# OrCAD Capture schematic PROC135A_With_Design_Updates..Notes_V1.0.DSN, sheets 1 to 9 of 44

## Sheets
1 01. TABLE OF CONTENTS: title: TABLE OF CONTENTS; rev: A
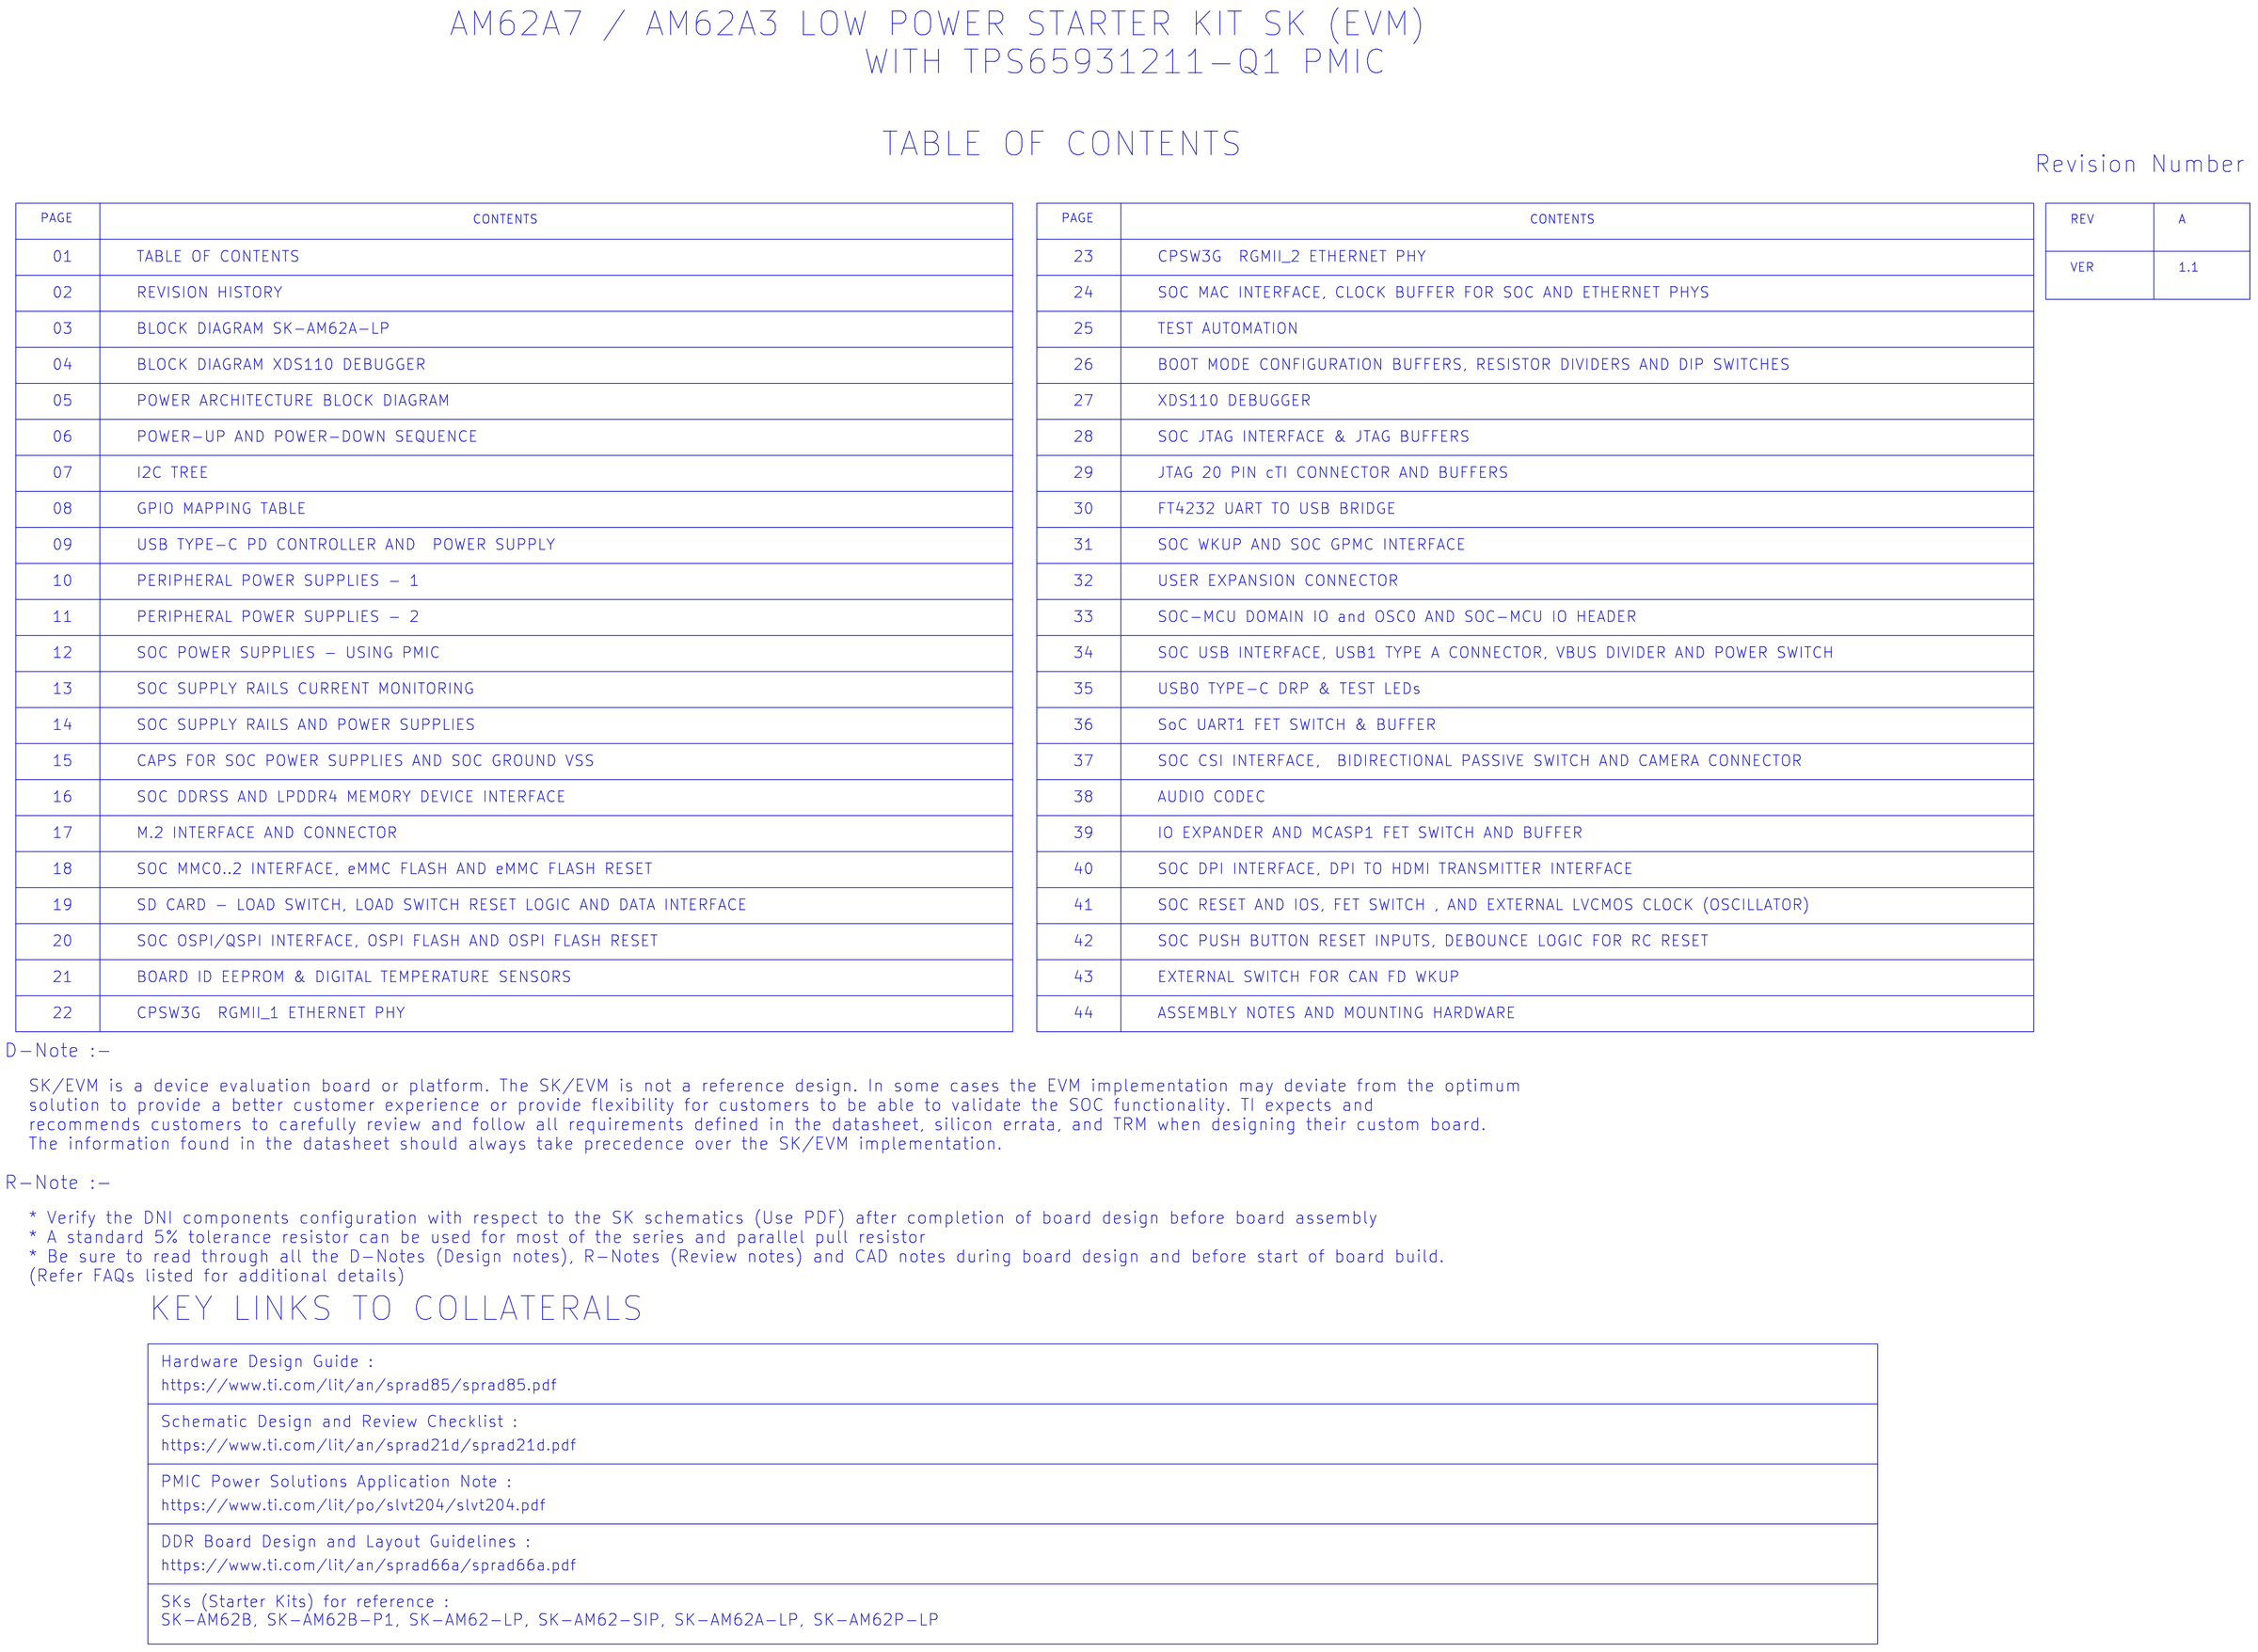
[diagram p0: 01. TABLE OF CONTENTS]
2 02. REVISION HISTORY: title: REVISION HISTORY
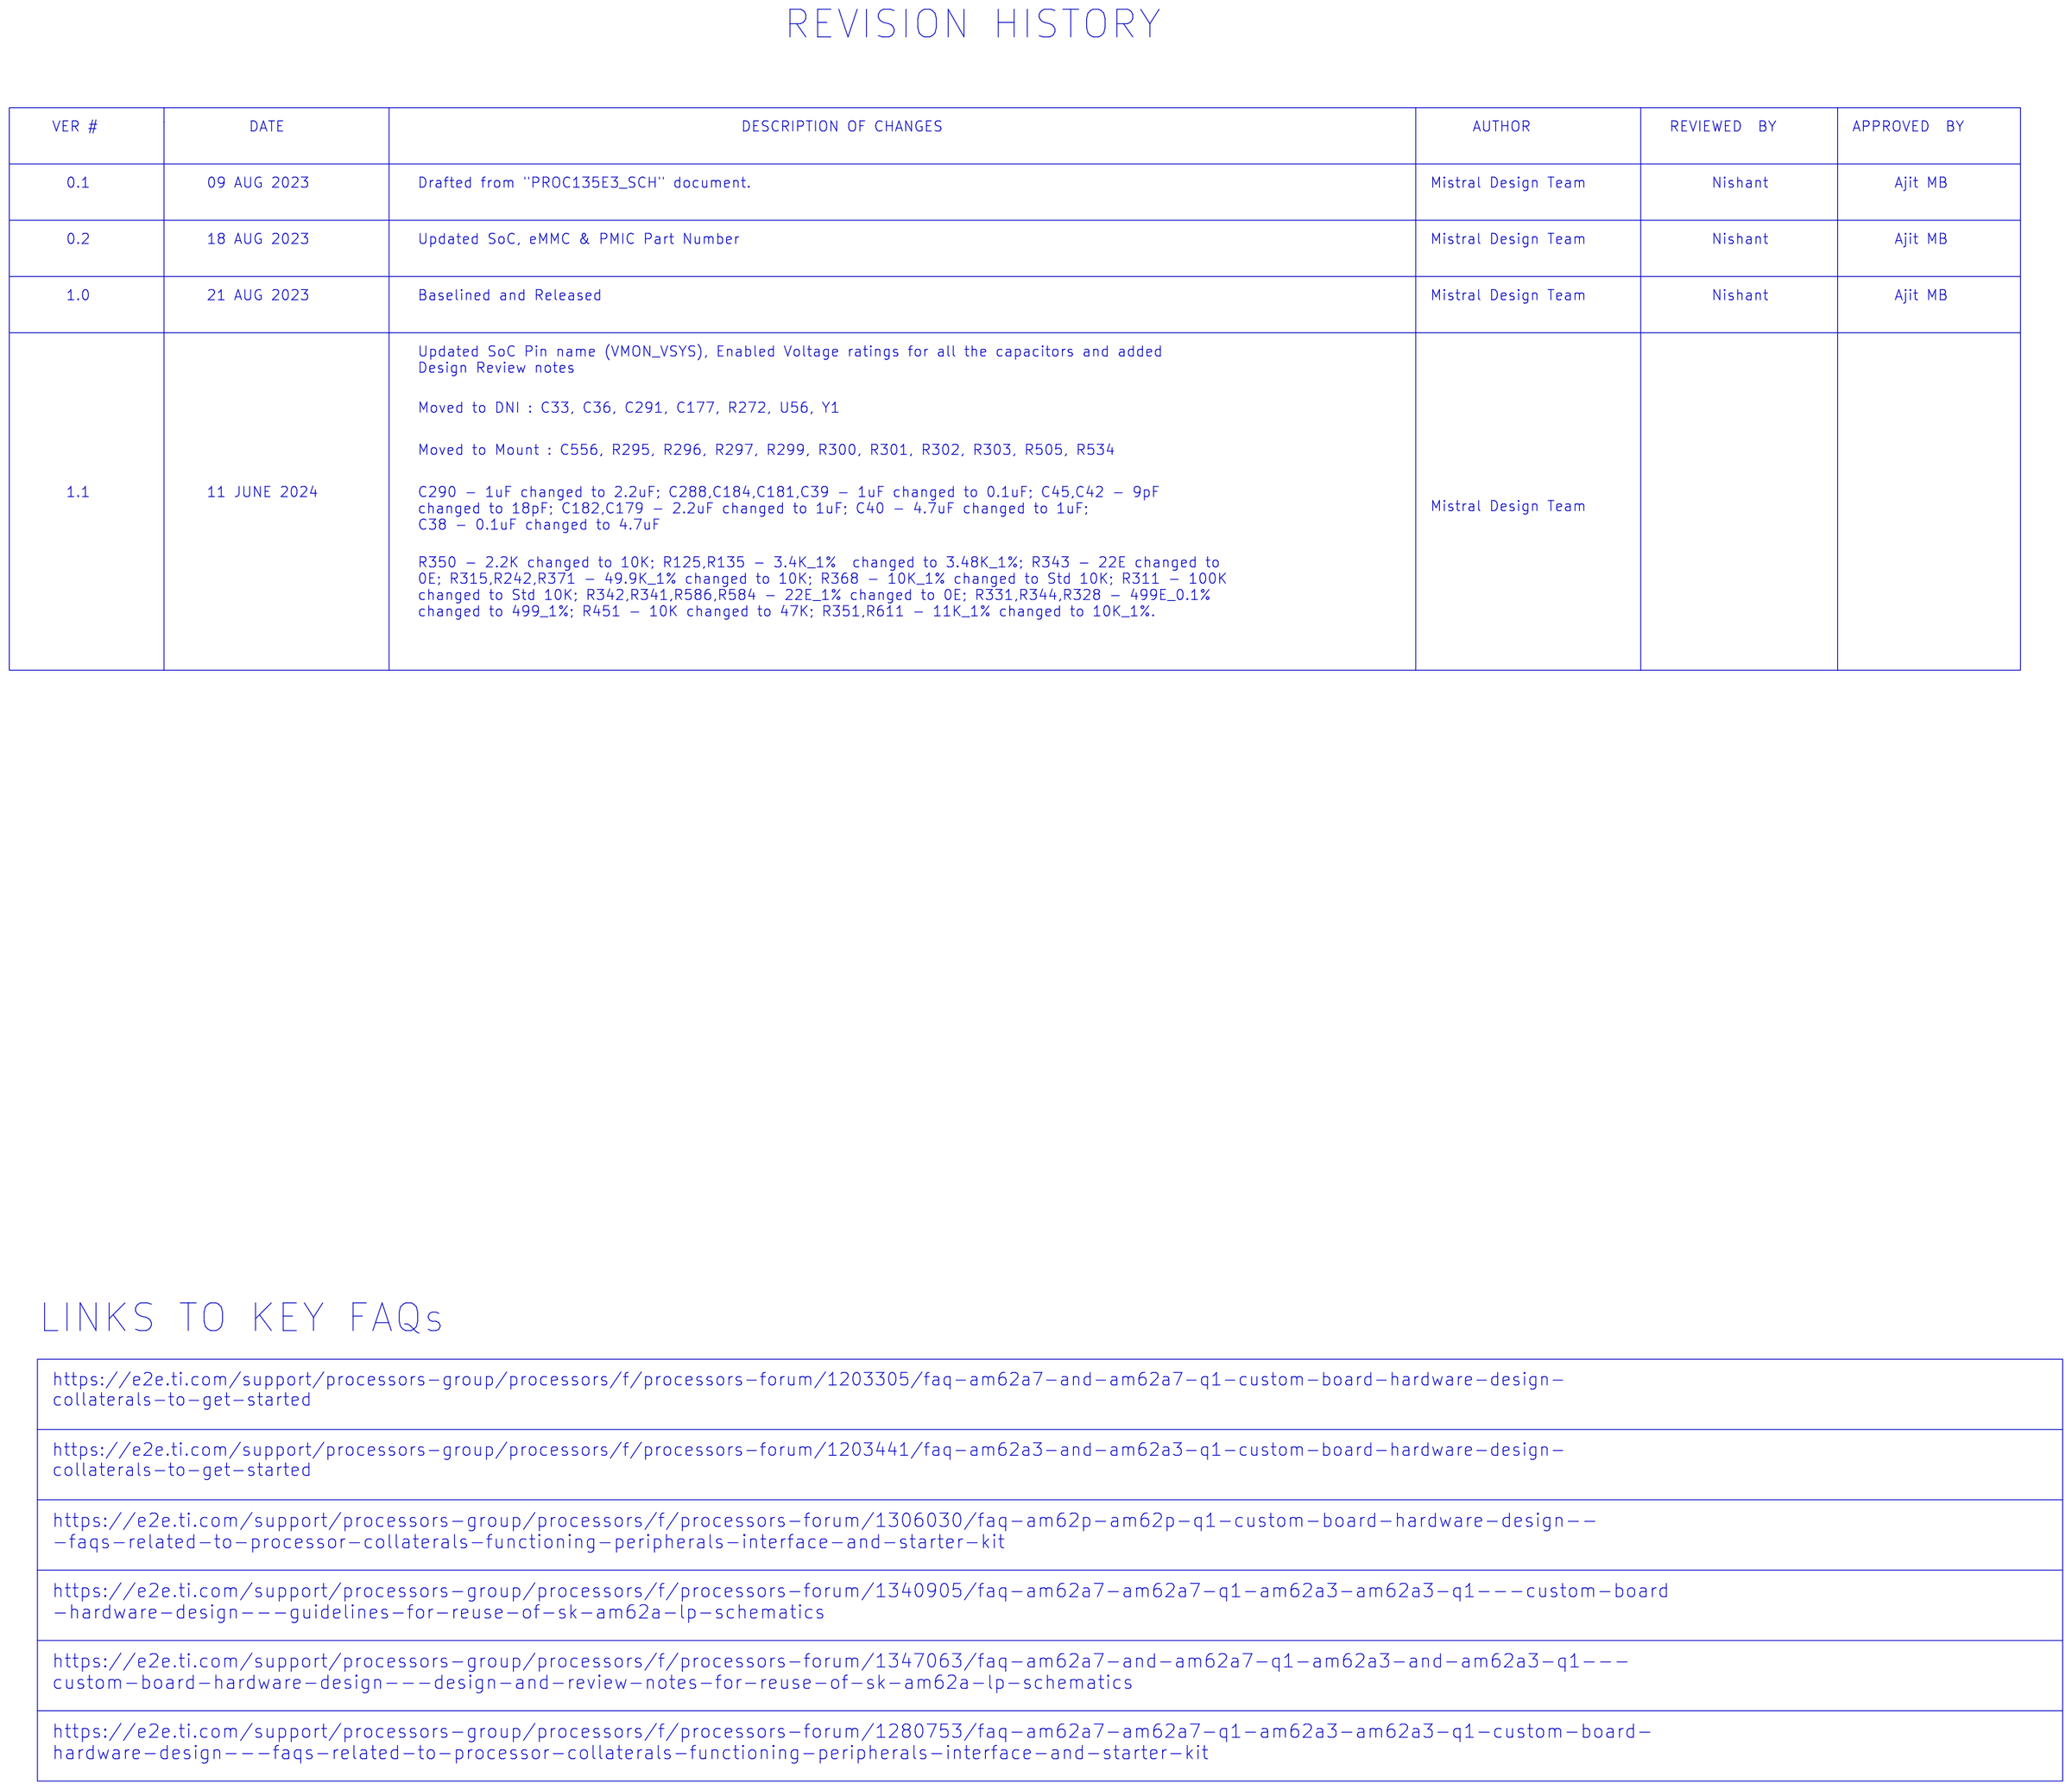
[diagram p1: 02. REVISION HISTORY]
3 03. BLOCK DGM AM62A-SKEVM: title: BLOCK DIAGRAM AM62A_ SKEVM
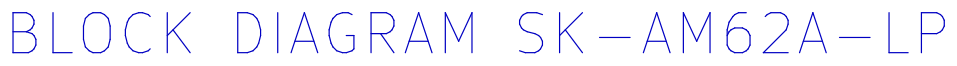
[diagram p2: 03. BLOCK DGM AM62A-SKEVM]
4 04. BLOCK DIAGRAM_XDS110: title: BLOCK DIAGRAM_XDS110
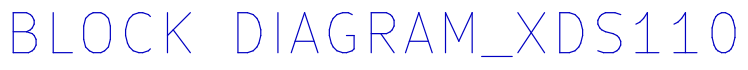
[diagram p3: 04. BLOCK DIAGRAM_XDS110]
5 05. POWER BLOCK DGM: title: POWER BLOCK DGM
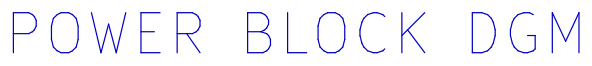
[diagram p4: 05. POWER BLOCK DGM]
6 06. POWER SEQUENCE: title: POWER SEQUENCE
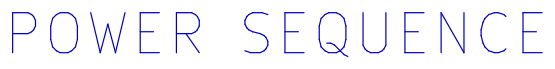
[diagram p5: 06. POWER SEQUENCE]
7 07. I2C TREE: title: I2C TREE
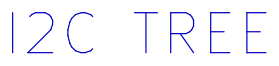
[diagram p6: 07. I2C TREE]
8 08. GPIO MAPPING TABLE: title: GPIO MAPPING TABLE
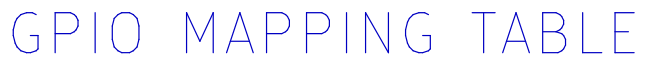
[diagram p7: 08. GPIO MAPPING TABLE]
9 09. USB TYPE-C POWER: size C; title: USB TYPE-C
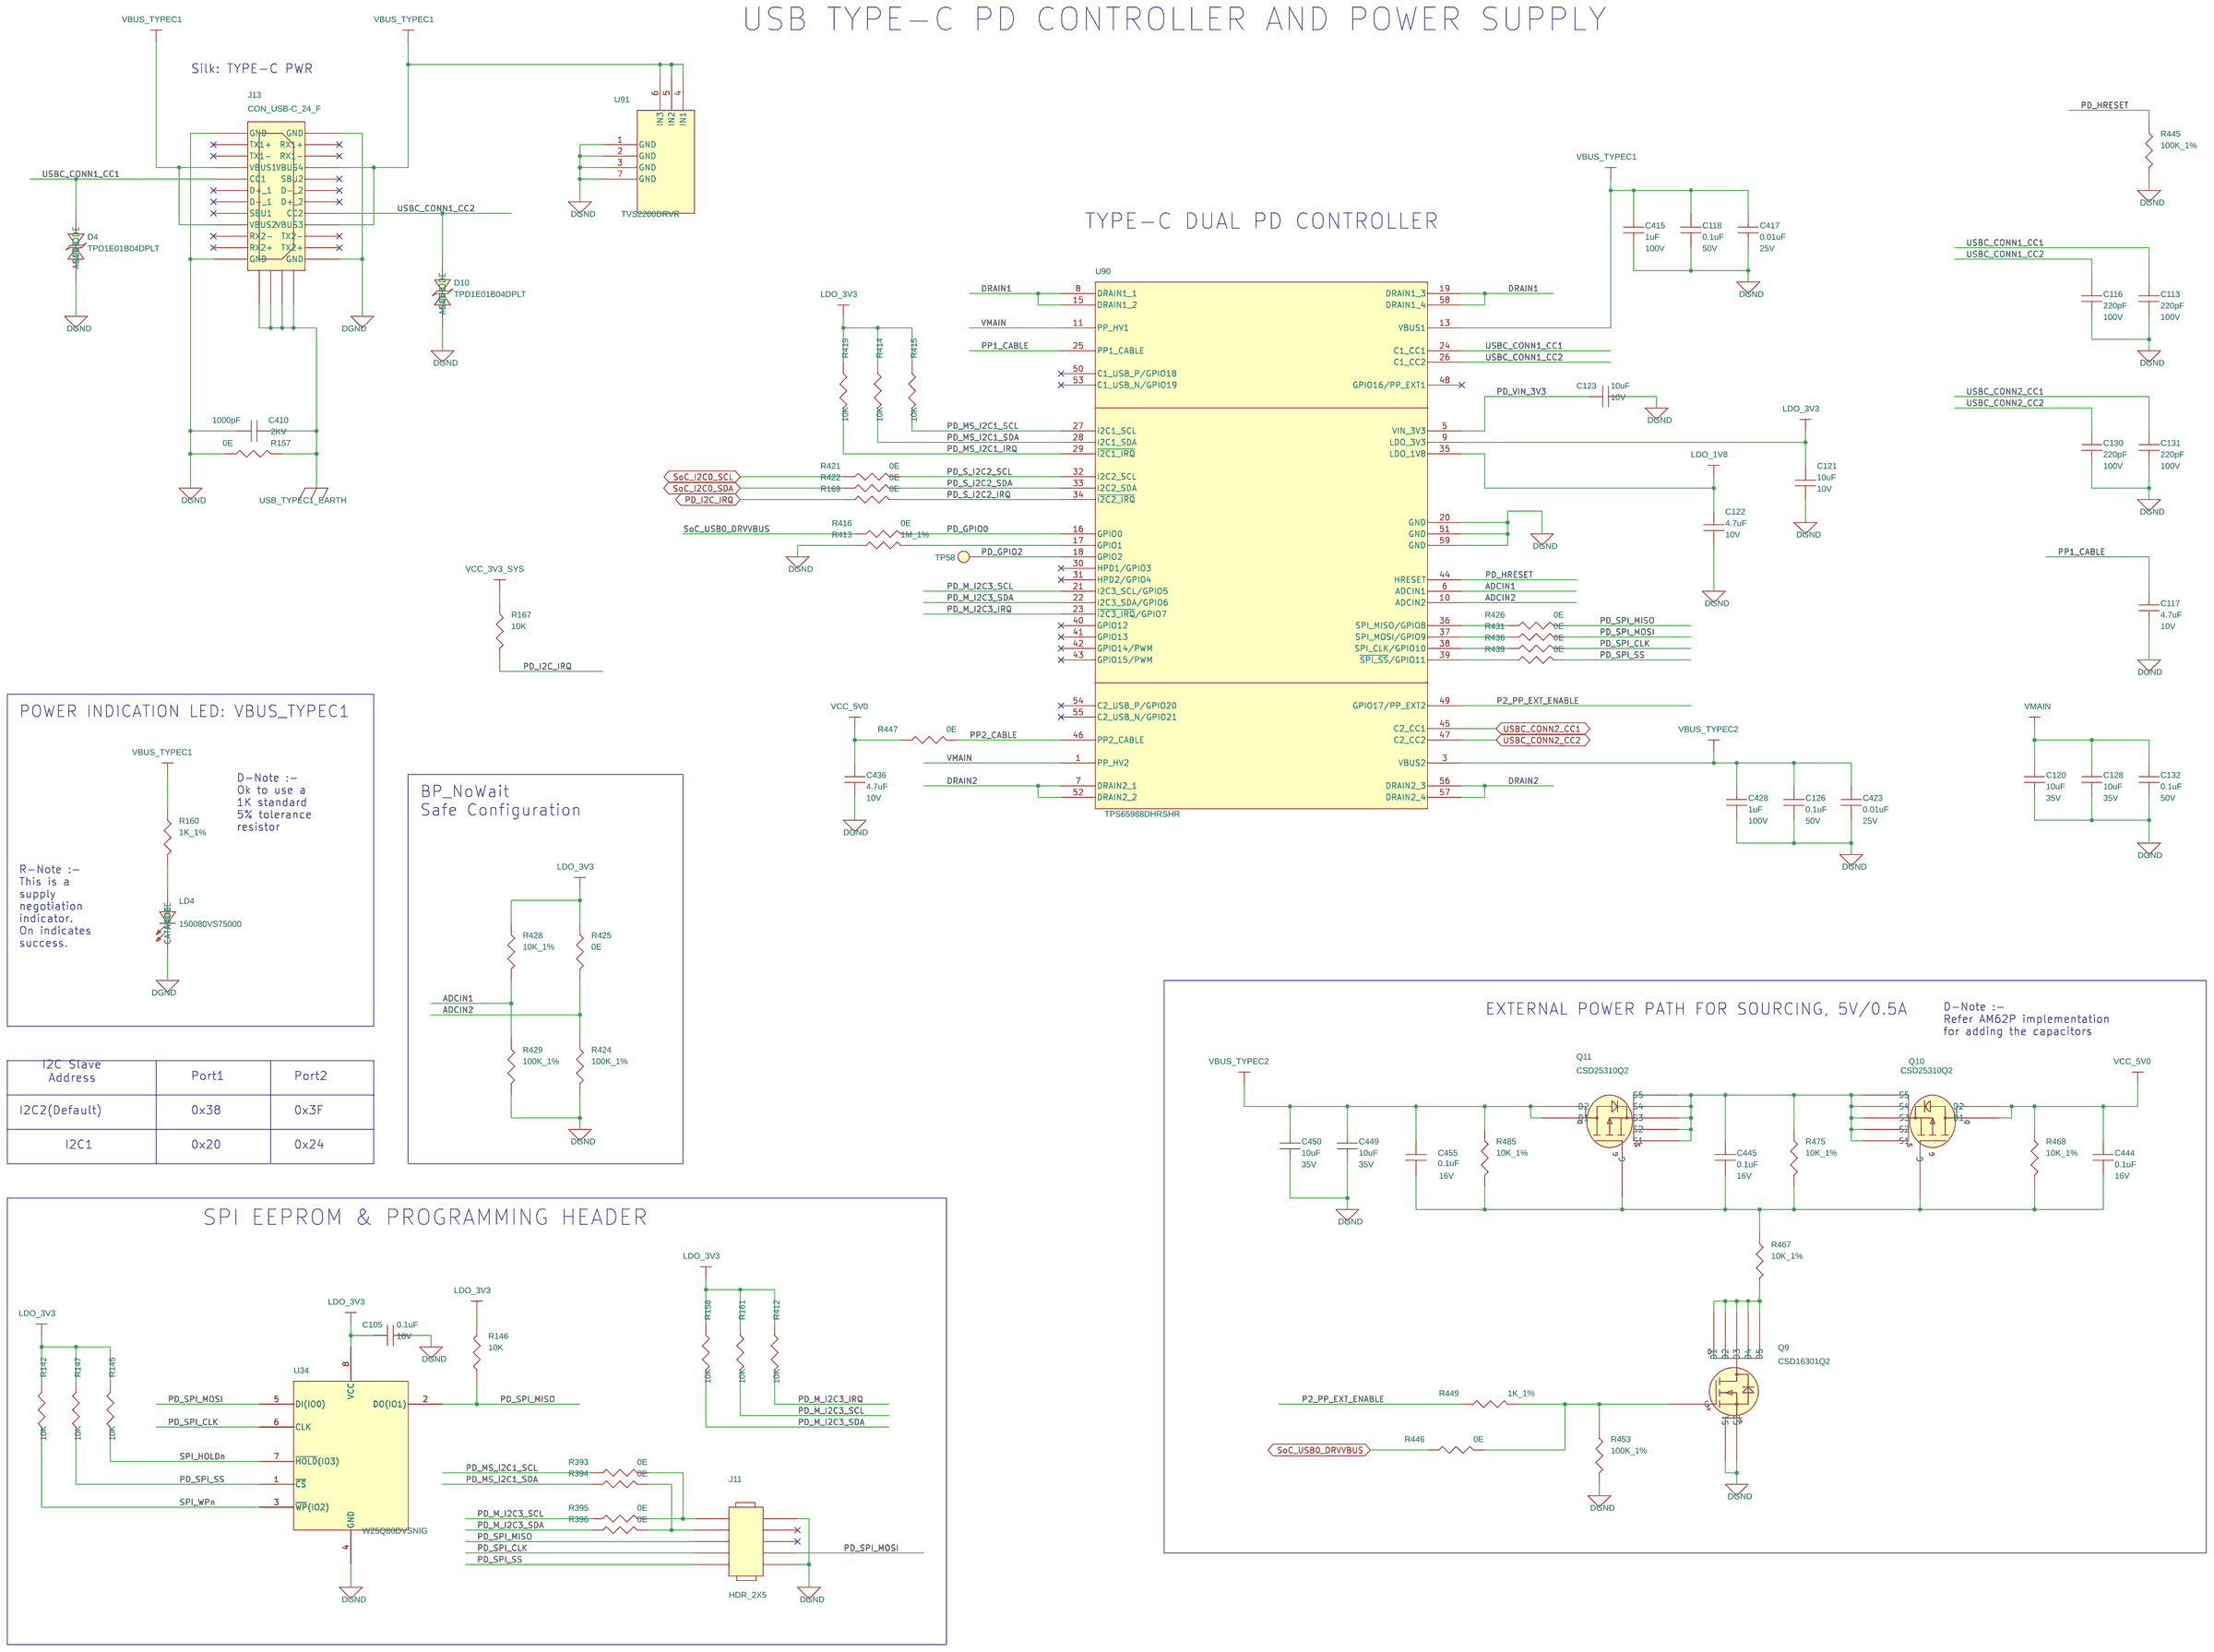
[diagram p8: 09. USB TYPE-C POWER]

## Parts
C105  0.1uF  [CAP0201_0-5]
C113  220pF  [CAP0402_0-75]
C116  220pF  [CAP0402_0-75]
C117  4.7uF  [CAP0402_0-75]
C118  0.1uF  [CAP0402_0-75]
C120  10uF  [CAP0603_1]
C121  10uF  [CAP0402_0-75]
C122  4.7uF  [CAP0402_0-75]
C123  10uF  [CAP0402_0-75]
C126  0.1uF  [CAP0402_0-75]
C128  10uF  [CAP0603_1]
C130  220pF  [CAP0402_0-75]
C131  220pF  [CAP0402_0-75]
C132  0.1uF  [CAP0402_0-75]
C410  1000pF  [CAP1206_1-75]
C415  1uF  [CAP0805_1-5]
C417  0.01uF  [CAP0201_0-5]
C423  0.01uF  [CAP0201_0-5]
C428  1uF  [CAP0805_1-5]
C436  4.7uF  [CAP0402_0-75]
C444  0.1uF  [CAP0201_0-5]
C445  0.1uF  [CAP0201_0-5]
C449  10uF  [CAP0603_1]
C450  10uF  [CAP0603_1]
C455  0.1uF  [CAP0201_0-5]
D4  TPD1E01B04DPLT  [DIO_DFN0201_0-4]
D10  TPD1E01B04DPLT  [DIO_DFN0201_0-4]
J11  HDR_2X5  [HDR_2X5_PEC05DAAN_S_T_8-6]
J13  CON_USB-C_24_F  [CON_USBC24_2012670_S_R_S_3-9]
LD4  150080VS75000  [LED_150080VS75000_80X50_SMD_0-8]
Q9  CSD16301Q2  [WSON6_CSD13202Q2_80X80_0-8]
Q10  CSD25310Q2  [SON6_CSD17313Q2_80X80]
Q11  CSD25310Q2  [SON6_CSD17313Q2_80X80]
R142  10K  [RES0201_0-5]
R145  10K  [RES0201_0-5]
R146  10K  [RES0201_0-5]
R147  10K  [RES0201_0-5]
R157  0E  [RES0603_0-75]
R158  10K  [RES0201_0-5]
R160  1K_1%  [RES0402_0-5]
R161  10K  [RES0201_0-5]
R167  10K  [RES0201_0-5]
R169  0E  [RES0201_0-5]
R393  0E  [RES0201_0-5]
R394  0E  [RES0201_0-5]
R395  0E  [RES0201_0-5]
R396  0E  [RES0201_0-5]
R412  10K  [RES0201_0-5]
R413  1M_1%  [RES0402_0-5]
R414  10K  [RES0201_0-5]
R415  10K  [RES0201_0-5]
R416  0E  [RES0201_0-5]
R419  10K  [RES0201_0-5]
R421  0E  [RES0201_0-5]
R422  0E  [RES0201_0-5]
R424  100K_1%  [RES0402_0-5]
R425  0E  [RES0201_0-5]
R426  0E  [RES0201_0-5]
R428  10K_1%  [RES0201_0-5]
R429  100K_1%  [RES0402_0-5]
R431  0E  [RES0201_0-5]
R436  0E  [RES0201_0-5]
R439  0E  [RES0201_0-5]
R445  100K_1%  [RES0201_0-5]
R446  0E  [RES0201_0-5]
R447  0E  [RES0402_0-5]
R449  1K_1%  [RES0402_0-5]
R453  100K_1%  [RES0402_0-5]
R467  10K_1%  [RES0201_0-5]
R468  10K_1%  [RES0201_0-5]
R475  10K_1%  [RES0201_0-5]
R485  10K_1%  [RES0201_0-5]
TP58  TP20_SMD  [TP20_SMD]
U34  W25Q80DVSNIG  [SOIC8_1-8]
U90  TPS65988DHRSHR  [VQFN56_TPS65987D_280X280_1]
U91  TVS2200DRVR  [SON6_25-59_85X85_0-8]

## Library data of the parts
C105 C444 C445 C455 = CAP: CAP CERAMIC 0.1uF 16V 10% X5R 0201; Chkd/date: MANIRAJA/230118; Crtd /date: MANIRAJA/230118; Custom_Duty: 15%; Customs_HS_Code: 85322990; Distributor_name: DIGIKEY; Distributor_part_number: 490-14305-1-ND; Footprint Path: Y:\MIS_DATABASE\Library\ALTIUM_TOOL\PCB_FOOTPRINTS\Altium_Footprint_Lib.PcbLib; Height: 0.33MM; Library Path: Y:\MIS_DATABASE\Library\ALTIUM_TOOL\SCHEMATICS_PARTS\MS_DISCRETE_Library.schlib; Mfr_name: MURATA; Mfr_part_number: GRM033R61C104KE14D; Mistral Part No: 120009030072-R; Package: 0201; Part_type: CAPACITORS\CERAMIC; Project: TI_MAXIE_CPB; RoHS: RoHS; Temperature: -55°C+85°C; Tolerance: 10%; Voltage: 16V; Wattage: NA; Weight: 0.33mg; Datasheet: Y:\MIS_DATABASE\DATASHEETS\CAPACITORS\GRM033R61C104KE14.PDF
C113 C116 C130 C131 = CAP: CAP CERAMIC 220pF 100V 5% C0G(NP0) 0402; Chkd/date: MANIRAJA/061021; Crtd /date: ALVY/051021; Custom_Duty: 15%; Customs_HS_Code: 85322990; Distributor_name: DIGIKEY; Distributor_part_number: 490-GRM1555C2A221JE01DTR-ND; Footprint Path: Y:\MIS_DATABASE\Library\ALTIUM_TOOL\PCB_FOOTPRINTS\Altium_Footprint_Lib.PcbLib; Height: 0.55MM; Library Path: Y:\MIS_DATABASE\Library\ALTIUM_TOOL\SCHEMATICS_PARTS\MS_DISCRETE_Library.schlib; Mfr_name: MURATA; Mfr_part_number: GRM1555C2A221JE01D; Mistral Part No: 120021100001-R; Package: 0402; Part_type: CAPACITORS\CERAMIC; Project: TI_AM62x SKEVM_BRD; RoHS: RoHS; Temperature: -55°C+125°C; Tolerance: 5%; Voltage: 100V; Wattage: NA; Weight: 1.6mg; Datasheet: Y:\MIS_DATABASE\DATASHEETS\CAPACITORS\GRM1555C2A221JE01.PDF
C117 C122 C436 = CAP: CAP CERAMIC 4.7uF 10V 20% X5R 0402; Chkd/date: MANIRAJA/110718; Crtd /date: ALVY/110718; Custom_Duty: 15%; Customs_HS_Code: 85322990; Distributor_name: DIGIKEY; Distributor_part_number: 490-14306-1-ND; Footprint Path: Y:\MIS_DATABASE\Library\ALTIUM_TOOL\PCB_FOOTPRINTS\Altium_Footprint_Lib.PcbLib; Height: 0.65MM; Library Path: Y:\MIS_DATABASE\Library\ALTIUM_TOOL\SCHEMATICS_PARTS\MS_DISCRETE_Library.schlib; Mfr_name: MURATA; Mfr_part_number: GRM155R61A475MEAAD; Mistral Part No: 120012060002-R; Package: 0402; Part_type: CAPACITORS\CERAMIC; Project: TI_J7SVB_PCIE_ADD-ON-CARD; RoHS: RoHS; Temperature: -55°C+85°C; Tolerance: 20%; Voltage: 10V; Wattage: NA; Weight: 14mg; Datasheet: Y:\MIS_DATABASE\DATASHEETS\CAPACITORS\GRM155R61A475MEAAD.PDF
C118 C126 C132 = CAP: CAP CERAMIC 0.1uF 50V 10% X7R 0402; Chkd/date: MANIRAJA/261020; Crtd /date: ALVY/211020; Custom_Duty: 15%; Customs_HS_Code: 85322990; Distributor_name: DIGIKEY; Distributor_part_number: 490-10700-1-ND; Footprint Path: Y:\MIS_DATABASE\Library\ALTIUM_TOOL\PCB_FOOTPRINTS\Altium_Footprint_Lib.PcbLib; Height: 0.55MM; Library Path: Y:\MIS_DATABASE\Library\ALTIUM_TOOL\SCHEMATICS_PARTS\MS_DISCRETE_Library.schlib; Mfr_name: MURATA; Mfr_part_number: GRM155R71H104KE14D; Mistral Part No: 120011100014-R; Package: 0402; Part_type: CAPACITORS\CERAMIC; Project: J7_CP; RoHS: RoHS; Temperature: -55°C+125°C; Tolerance: 10%; Voltage: 50V; Wattage: NA; Weight: 3.1mg; Datasheet: Y:\MIS_DATABASE\DATASHEETS\CAPACITORS\GRM155R71H104KE14.PDF
C120 C128 C449 C450 = CAP: CAP CERAMIC 10uF 35V 20% X5R 0603; Chkd/date: MANIRAJA/170519; Crtd /date: ALVY/160519; Custom_Duty: 15%; Customs_HS_Code: 85322990; Distributor_name: DIGIKEY; Distributor_part_number: 490-13248-1-ND; Footprint Path: Y:\MIS_DATABASE\Library\ALTIUM_TOOL\PCB_FOOTPRINTS\Altium_Footprint_Lib.PcbLib; Height: 1.00MM; Library Path: Y:\MIS_DATABASE\Library\ALTIUM_TOOL\SCHEMATICS_PARTS\MS_DISCRETE_Library.schlib; Mfr_name: MURATA; Mfr_part_number: GRM188R6YA106MA73D; Mistral Part No: 120019050016-R; Package: 0603; Part_type: CAPACITORS\CERAMIC; Project: BRUKER_SD820_COMMONDO; RoHS: RoHS; Temperature: -55°C+85°C; Tolerance: 20%; Voltage: 35V; Wattage: NA; Weight: 9mg; Datasheet: Y:\MIS_DATABASE\DATASHEETS\CAPACITORS\GRM188R6YA106MA73.PDF
C121 C123 = CAP: CAP CERAMIC 10uF 10V 20% X5R 0402; Chkd/date: MANIRAJA/300520; Crtd /date: ALVY/260520; Custom_Duty: 15%; Customs_HS_Code: 85322990; Distributor_name: DIGIKEY; Distributor_part_number: 490-GRM155R61A106ME11DTR-ND; Footprint Path: Y:\MIS_DATABASE\Library\ALTIUM_TOOL\PCB_FOOTPRINTS\Altium_Footprint_Lib.PcbLib; Height: 0.55MM; Library Path: Y:\MIS_DATABASE\Library\ALTIUM_TOOL\SCHEMATICS_PARTS\MS_DISCRETE_Library.schlib; Mfr_name: MURATA; Mfr_part_number: GRM155R61A106ME11D; Mistral Part No: 120013110019-R; Package: 0402; Part_type: CAPACITORS\CERAMIC; Project: QCS610_NANOSOM; RoHS: RoHS; Temperature: -55°C+85°C; Tolerance: 20%; Voltage: 10V; Wattage: NA; Weight: 3.1mg; Datasheet: Y:\MIS_DATABASE\DATASHEETS\CAPACITORS\MURATA-GXX-SER_NOV17.PDF
C410 = CAP: CAP CERAMIC 1000pF 2KV 10% X7R 1206; Chkd/date: SHREESHAIL/291106; Crtd /date: MAZHAR/281106; Custom_Duty: 15%; Customs_HS_Code: 85322990; Distributor_name: DIGIKEY; Distributor_part_number: 478-2956-1-ND; Footprint Path: Y:\MIS_DATABASE\Library\ALTIUM_TOOL\PCB_FOOTPRINTS\Altium_Footprint_Lib.PcbLib; Height: 1.52MM; Library Path: Y:\MIS_DATABASE\Library\ALTIUM_TOOL\SCHEMATICS_PARTS\MS_DISCRETE_Library.schlib; Mfr_name: AVX CORPORATION; Mfr_part_number: 1206GC102KAT1A; Mistral Part No: 120015080006-R; Package: 1206; Part_type: CAPACITORS\CERAMIC; Project: ADR1B; RoHS: RoHS; Temperature: -55°C+125°C; Tolerance: 10%; Voltage: 2KV; Wattage: NA; Weight: 16.2mg; Datasheet: Y:\MIS_DATABASE\DATASHEETS\CAPACITORS\AVX_HV-MLC.PDF
C415 C428 = CAP: CAP CERAMIC 1uF 100V 10% X7S 0805; Chkd/date: MANIRAJA/160921; Crtd /date: ALVY/150921; Custom_Duty: 15%; Customs_HS_Code: 85322990; Distributor_name: DIGIKEY; Distributor_part_number: 490-14464-1-ND; Footprint Path: Y:\MIS_DATABASE\Library\ALTIUM_TOOL\PCB_FOOTPRINTS\Altium_Footprint_Lib.PcbLib; Height: 1.45MM; Library Path: Y:\MIS_DATABASE\Library\ALTIUM_TOOL\SCHEMATICS_PARTS\MS_DISCRETE_Library.schlib; Mfr_name: MURATA; Mfr_part_number: GRM21BC72A105KE01L; Mistral Part No: 120013030002-R; Package: 0805; Part_type: CAPACITORS\CERAMIC; Project: TI_AM62x SKEVM_BRD; RoHS: RoHS; Temperature: -55°C+125°C; Tolerance: 10%; Voltage: 100V; Wattage: NA; Weight: 6.4mg; Datasheet: Y:\MIS_DATABASE\DATASHEETS\CAPACITORS\GRM21BC72A105KE01.PDF
C417 C423 = CAP: CAP CERAMIC 0.01uF 25V 10% X5R 0201; Chkd/date: MANIRAJA/230118; Crtd /date: MANIRAJA/230118; Custom_Duty: 15%; Customs_HS_Code: 85322990; Distributor_name: DIGIKEY; Distributor_part_number: GRM033R61E103KA12J-ND; Footprint Path: Y:\MIS_DATABASE\Library\ALTIUM_TOOL\PCB_FOOTPRINTS\Altium_Footprint_Lib.PcbLib; Height: 0.33MM; Library Path: Y:\MIS_DATABASE\Library\ALTIUM_TOOL\SCHEMATICS_PARTS\MS_DISCRETE_Library.schlib; Mfr_name: MURATA; Mfr_part_number: GRM033R61E103KA12J; Mistral Part No: 120018010007-R; Package: 0201; Part_type: CAPACITORS\CERAMIC; Project: TI_MAXIE_CPB; RoHS: RoHS; Temperature: -55°C+85°C; Tolerance: 10%; Voltage: 25V; Wattage: NA; Weight: 0.33mg; Datasheet: Y:\MIS_DATABASE\DATASHEETS\CAPACITORS\GRM033R61E103KA12.PDF
D4 D10 = DIODE_TVS_DUAL: DIODE 1CH ESD PROTECTION FOR USB TYPE-C AND THUNDERBOLT3 X2SON2; Chkd/date: MANIRAJA/230920; Crtd /date: ALVY/230920; Custom_Duty: 15%; Customs_HS_Code: 85412900; Distributor_name: DIGIKEY; Distributor_part_number: 296-44484-1-ND; Footprint Path: Y:\MIS_DATABASE\Library\ALTIUM_TOOL\PCB_FOOTPRINTS\Altium_Footprint_Lib.PcbLib; Height: 0.32MM; Library Path: Y:\MIS_DATABASE\Library\ALTIUM_TOOL\SCHEMATICS_PARTS\MS_DISCRETE_Library.schlib; Mfr_name: TEXAS INSTRUMENTS; Mistral Part No: 130020090037-R; Package: X2SON2; Part_type: DIODE\TVS; Project: AM64X_SKEVM; RoHS: RoHS; Temperature: -40°C+125°C; Tolerance: NA; Voltage: NA; Wattage: NA; Weight: 0.2mg; Datasheet: Y:\MIS_DATABASE\DATASHEETS\DISCRETES\DIODES\TPD1E01B04.PDF
J11 = HEADER_5X2: CON HDR 2X5 2.54MM PITCH ST TH; Chkd/date: MANIRAJA/060821; Crtd /date: ALVY/060821; Custom_Duty: 24%; Customs_HS_Code: 85369090; Distributor_name: DIGIKEY; Distributor_part_number: S2012E-05-ND; Footprint Path: Y:\MIS_DATABASE\Library\ALTIUM_TOOL\PCB_FOOTPRINTS\Altium_Footprint_Lib.PcbLib; Height: 8.58MM; Library Path: Y:\MIS_DATABASE\Library\ALTIUM_TOOL\SCHEMATICS_PARTS\MS_CONNECTOR_Library.schlib; Mfr_name: SULLINS CONNECTOR; Mfr_part_number: PEC05DAAN; Mistral Part No: 150021080010-R; Package: THRU-HOLE; Part_type: CONNECTOR\HEADERS; Project: TI_AM335x SK_BRD; RoHS: RoHS; Temperature: -65°C+125°C; Tolerance: NA; Voltage: NA; Wattage: NA; Weight: NA; Datasheet: Y:\MIS_DATABASE\DATASHEETS\CONNECTORS\XXCXXDXXN.PDF
J13 = CON_USB-C_24_1240183621: CON USB-C TYPE 24POS FEMALE RT SMD; Chkd/date: MANIRAJA/050618; Crtd /date: ALVY/040618; Custom_Duty: 24%; Customs_HS_Code: 85369090; Distributor_name: DIGIKEY; Distributor_part_number: WM17992CT-ND; Footprint Path: Y:\MIS_DATABASE\Library\ALTIUM_TOOL\PCB_FOOTPRINTS\Altium_Footprint_Lib.PcbLib; Height: 3.86MM; Library Path: Y:\MIS_DATABASE\Library\ALTIUM_TOOL\SCHEMATICS_PARTS\MS_CONNECTOR_Library.schlib; Mfr_name: MOLEX; Mfr_part_number: 2012670005; Mistral Part No: 150018060002-R; Package: SMD; Part_type: CONNECTOR\USB; Project: TI_J7SVB_USB_ADD-ON-CARD; RoHS: RoHS; Temperature: -40°C+105°C; Tolerance: NA; Voltage: NA; Wattage: NA; Weight: 0.686g; Datasheet: Y:\MIS_DATABASE\DATASHEETS\CONNECTORS\2012670X.PDF
LD4 = DIODE_LED: DIODE LED BRIGHT GREEN SMD; Chkd/date: MANIRAJA/180820; Crtd /date: ALVY/180820; Custom_Duty: 24%; Customs_HS_Code: 85439000; Distributor_name: DIGIKEY; Distributor_part_number: 732-4986-1-ND; Footprint Path: Y:\MIS_DATABASE\Library\ALTIUM_TOOL\PCB_FOOTPRINTS\Altium_Footprint_Lib.PcbLib; Height: 0.80MM; Library Path: Y:\MIS_DATABASE\Library\ALTIUM_TOOL\SCHEMATICS_PARTS\MS_OPTO_Library.schlib; Mfr_name: WURTH ELECTRONICS; Mistral Part No: 130020080012-R; Package: SMD; Part_type: OPTO\LED; Project: AM64x_EVM_BRD; RoHS: RoHS; Temperature: -40°C+85°C; Tolerance: NA; Voltage: NA; Wattage: NA; Weight: 10mg; Datasheet: Y:\MIS_DATABASE\DATASHEETS\DISCRETES\LEDS\150080VS75000.PDF
Q9 = MOSFET_CSD17313Q2: IC MOSFET N-CHANNEL NEXFET 25V WSON6; Chkd/date: ALVY/071220; Crtd /date: MANIRAJA/071220; Custom_Duty: 15%; Customs_HS_Code: 85423100; Distributor_name: DIGIKEY; Distributor_part_number: 296-25260-1-ND; Footprint Path: Y:\MIS_DATABASE\Library\ALTIUM_TOOL\PCB_FOOTPRINTS\Altium_Footprint_Lib.PcbLib; Height: 0.80MM; Library Path: Y:\MIS_DATABASE\Library\ALTIUM_TOOL\SCHEMATICS_PARTS\MS_MOSFET_Library.schlib; Mfr_name: TEXAS INSTRUMENTS; Mistral Part No: 142020120008-R; Package: WSON6; Part_type: ICS\POWER\MOSFET; Project: TI_AM243x LP EVM; RoHS: RoHS; Temperature: -55°C+150°C; Tolerance: NA; Voltage: NA; Wattage: NA; Weight: 8.7mg; Datasheet: Y:\MIS_DATABASE\DATASHEETS\ICS\POWER\CSD16301Q2.PDF
Q10 Q11 = MOSFET_CSD25310Q2: IC MOSFET P-CHANNEL WSON6; Chkd/date: VASANTHA/191215; Crtd /date: VASANTHA/191215; Custom_Duty: 15%; Customs_HS_Code: 85423100; Distributor_name: DIGIKEY; Distributor_part_number: 296-38915-1-ND; Height: 0.85MM; Mfr_name: TEXAS INSTRUMENTS; Mistral Part No: 142015120011-R; Package: WSON6; Part_type: ICS\POWER\MOSFET; Project: DUET BOARD; RoHS: RoHS; Temperature: -55°C+150°C; Tolerance: NA; Voltage: NA; Wattage: NA; Weight: NA; Datasheet: Y:\MIS_DATABASE\DATASHEETS\DISCRETES\TRANSISTORS_FETS\CSD25310Q2.PDF
R142 R145-R147 R158 R161 R167 R412 R414 R415 R419 = RESISTOR: RES 10K 1/20W 5% 0201; Chkd/date: MANIRAJA/050517; Crtd /date: MANIRAJA/050517; Custom_Duty: 15%; Customs_HS_Code: 85332119; Distributor_name: DIGIKEY; Distributor_part_number: 311-10KNCT-ND; Footprint Path: Y:\MIS_DATABASE\Library\ALTIUM_TOOL\PCB_FOOTPRINTS\Altium_Footprint_Lib.PcbLib; Height: 0.26MM; Library Path: Y:\MIS_DATABASE\Library\ALTIUM_TOOL\SCHEMATICS_PARTS\MS_DISCRETE_Library.schlib; Mfr_name: YAGEO AMERICA; Mfr_part_number: RC0201JR-0710KL; Mistral Part No: 110010070051-R; Package: 0201; Part_type: RESISTORS\FIXED; Project: GOLDEN-I LITE; RoHS: RoHS; Temperature: -55°C+125°C; Tolerance: 5%; Voltage: NA; Wattage: 1/20W; Weight: 0.17mg; Datasheet: Y:\MIS_DATABASE\DATASHEETS\RESISTORS\RCXXXXL-SER_MAR18.PDF
R157 = RESISTOR: RES 0E 1/10W 5% 0603; Chkd/date: MANIRAJA/051217; Crtd /date: BAVISH/180211; Custom_Duty: 15%; Customs_HS_Code: 85332119; Distributor_name: DIGIKEY; Distributor_part_number: 311-0.0GRCT-ND; Footprint Path: Y:\MIS_DATABASE\Library\ALTIUM_TOOL\PCB_FOOTPRINTS\Altium_Footprint_Lib.PcbLib; Height: 0.55MM; Library Path: Y:\MIS_DATABASE\Library\ALTIUM_TOOL\SCHEMATICS_PARTS\MS_DISCRETE_Library.schlib; Manufacturer: YAGEO AMERICA; Mfr_name: PANASONIC-ECG; Mfr_part_number: RC0603JR-070RL; Mistral Part No: 110011020013-R; Package: 0603; Part_type: RESISTORS\FIXED; Project: KENNEL; RoHS: RoHS; Temperature: -55°C+155°C; Tolerance: 5%; Voltage: NA; Wattage: 1/10W; Weight: 2mg; Datasheet: Y:\MIS_DATABASE\DATASHEETS\RESISTORS\RCXXXXL-SER_MAR18.PDF
R160 R449 = RESISTOR: RES 1K 1/10W 1% 0402; Chkd/date: VASANTHA/281216; Crtd /date: MAZHAR/150506; Custom_Duty: 15%; Customs_HS_Code: 85332119; Distributor_name: DIGIKEY; Distributor_part_number: P1.00KLCT-ND; Footprint Path: Y:\MIS_DATABASE\Library\ALTIUM_TOOL\PCB_FOOTPRINTS\Altium_Footprint_Lib.PcbLib; Height: 0.40MM; Library Path: Y:\MIS_DATABASE\Library\ALTIUM_TOOL\SCHEMATICS_PARTS\MS_DISCRETE_Library.schlib; Mfr_name: PANASONIC-ECG; Mfr_part_number: ERJ-2RKF1001X; Mistral Part No: 110009030411-R; Package: 0402; Part_type: RESISTORS\FIXED; Project: VOCERA; RoHS: RoHS; Temperature: -55°C+155°C; Tolerance: 1%; Voltage: NA; Wattage: 1/10W; Weight: 0.8mg; Datasheet: Y:\MIS_DATABASE\DATASHEETS\RESISTORS\PAN-ERJSER_NOV17.PDF
R169 R393-R396 R416 R421 R422 R426 R431 R436 R439 R446 = RESISTOR: RES 0E 1/20W 5% 0201; Chkd/date: NAVEED/301214; Crtd /date: MUDDU/120710; Custom_Duty: 15%; Customs_HS_Code: 85332119; Distributor_name: DIGIKEY; Distributor_part_number: 311-0.0NCT-ND; Footprint Path: Y:\MIS_DATABASE\Library\ALTIUM_TOOL\PCB_FOOTPRINTS\Altium_Footprint_Lib.PcbLib; Height: 0.26MM; Library Path: Y:\MIS_DATABASE\Library\ALTIUM_TOOL\SCHEMATICS_PARTS\MS_DISCRETE_Library.schlib; Mfr_name: YAGEO AMERICA; Mfr_part_number: RC0201JR-070RL; Mistral Part No: 110010070067-R; Package: 0201; Part_type: RESISTORS\FIXED; Project: PB_BUGBASE; RoHS: RoHS; Temperature: -55°C+125°C; Tolerance: 5%; Voltage: NA; Wattage: 1/20W; Weight: 0.17mg; Datasheet: Y:\MIS_DATABASE\DATASHEETS\RESISTORS\RCXXXXL-SER_MAR18.PDF
R413 = RESISTOR: RES 1M 1/16W 1% 0402; Chkd/date: MANIRAJA/190319; Crtd /date: MANIRAJA/190319; Custom_Duty: 15%; Customs_HS_Code: 85332119; Distributor_name: DIGIKEY; Distributor_part_number: 311-1.00MLRCT-ND; Footprint Path: Y:\MIS_DATABASE\Library\ALTIUM_TOOL\PCB_FOOTPRINTS\Altium_Footprint_Lib.PcbLib; Height: 0.40MM; Library Path: Y:\MIS_DATABASE\Library\ALTIUM_TOOL\SCHEMATICS_PARTS\MS_DISCRETE_Library.schlib; Mfr_name: YAGEO AMERICA; Mfr_part_number: RC0402FR-071ML; Mistral Part No: 110014060045-R; Package: 0402; Part_type: RESISTORS\FIXED; Project: G4SLIM; RoHS: RoHS; Temperature: -55°C+155°C; Tolerance: 1%; Voltage: NA; Wattage: 1/16W; Weight: 0.65mg; Datasheet: Y:\MIS_DATABASE\DATASHEETS\RESISTORS\RCXXXXL-SER_MAR18.PDF
R424 R429 R453 = RESISTOR: RES 100K 1/10W 1% 0402; Chkd/date: VASANTHA/201216; Crtd /date: MAZHAR/130306; Custom_Duty: 15%; Customs_HS_Code: 85332119; Distributor_name: DIGIKEY; Distributor_part_number: P100KLCT-ND; Footprint Path: Y:\MIS_DATABASE\Library\ALTIUM_TOOL\PCB_FOOTPRINTS\Altium_Footprint_Lib.PcbLib; Height: 0.40MM; Library Path: Y:\MIS_DATABASE\Library\ALTIUM_TOOL\SCHEMATICS_PARTS\MS_DISCRETE_Library.schlib; Mfr_name: PANASONIC-ECG; Mfr_part_number: ERJ-2RKF1003X; Mistral Part No: 110009030187-R; Package: 0402; Part_type: RESISTORS\FIXED; Project: J32; RoHS: RoHS; Temperature: -55°C+155°C; Tolerance: 1%; Voltage: NA; Wattage: 1/10W; Weight: 0.8mg; Datasheet: Y:\MIS_DATABASE\DATASHEETS\RESISTORS\PAN-ERJSER_NOV17.PDF
R425 = RESISTOR: RES 0E 1/20W JUMPER 0201; Chkd/date: VASANTHA/061216; Crtd /date: MAZHAR/040505; Custom_Duty: 15%; Customs_HS_Code: 85332119; Distributor_name: DIGIKEY; Distributor_part_number: P0.0AGCT-ND; Footprint Path: Y:\MIS_DATABASE\Library\ALTIUM_TOOL\PCB_FOOTPRINTS\Altium_Footprint_Lib.PcbLib; Height: 0.26MM; Library Path: Y:\MIS_DATABASE\Library\ALTIUM_TOOL\SCHEMATICS_PARTS\MS_DISCRETE_Library.schlib; Mfr_name: PANASONIC-ECG; Mfr_part_number: ERJ-1GE0R00C; Mistral Part No: 110009030078-R; Package: 0201; Part_type: RESISTORS\FIXED; Project: HS100RD; RoHS: RoHS; Temperature: -55°C+125°C; Tolerance: NA; Voltage: NA; Wattage: 1/20W; Weight: 0.15mg; Datasheet: Y:\MIS_DATABASE\DATASHEETS\RESISTORS\PAN-ERJXGE-FEB06.PDF
R428 R467 R475 = RESISTOR: RES 10K 1/20W 1% 0201; Chkd/date: VASANTHA/270117; Crtd /date: MANIRAJA/270117; Custom_Duty: 15%; Customs_HS_Code: 85332119; Distributor_name: DIGIKEY; Distributor_part_number: 311-10.0KMCT-ND; Footprint Path: Y:\MIS_DATABASE\Library\ALTIUM_TOOL\PCB_FOOTPRINTS\Altium_Footprint_Lib.PcbLib; Height: 0.26MM; Library Path: Y:\MIS_DATABASE\Library\ALTIUM_TOOL\SCHEMATICS_PARTS\MS_DISCRETE_Library.schlib; Mfr_name: YAGEO AMERICA; Mfr_part_number: RC0201FR-0710KL; Mistral Part No: 110011040018-R; Package: 0201; Part_type: RESISTORS\FIXED; Project: GOLDEN-I LITE; RoHS: RoHS; Temperature: -55°C+125°C; Tolerance: 1%; Voltage: NA; Wattage: 1/20W; Weight: 0.17mg; Datasheet: Y:\MIS_DATABASE\DATASHEETS\RESISTORS\RCXXXXL-SER_MAR18.PDF
R445 = RESISTOR: RES 100K 1/20W 1% 0201; Chkd/date: MANIRAJA/120520; Crtd /date: ALVY/120520; Custom_Duty: 15%; Customs_HS_Code: 85332119; Distributor_name: DIGIKEY; Distributor_part_number: 311-100KMCT-ND; Footprint Path: Y:\MIS_DATABASE\Library\ALTIUM_TOOL\PCB_FOOTPRINTS\Altium_Footprint_Lib.PcbLib; Height: 0.26MM; Library Path: Y:\MIS_DATABASE\Library\ALTIUM_TOOL\SCHEMATICS_PARTS\MS_DISCRETE_Library.schlib; Mfr_name: YAGEO AMERICA; Mfr_part_number: RC0201FR-07100KL; Mistral Part No: 110009060005-R; Package: 0201; Part_type: RESISTORS\FIXED; Project: SD865_NANOSOM; RoHS: RoHS; Temperature: -55°C+125°C; Tolerance: 1%; Voltage: NA; Wattage: 1/20W; Weight: 9mg; Datasheet: Y:\MIS_DATABASE\DATASHEETS\RESISTORS\RCXXXXL-SER_MAR18.PDF
R447 = RESISTOR: RES 0E 1/16W JUMPER 0402; Chkd/date: VASANTHA/201216; Crtd /date: MUDDU/190810; Custom_Duty: 15%; Customs_HS_Code: 85332119; Distributor_name: DIGIKEY; Distributor_part_number: 541-0.0JCT-ND; Footprint Path: Y:\MIS_DATABASE\Library\ALTIUM_TOOL\PCB_FOOTPRINTS\Altium_Footprint_Lib.PcbLib; Height: 0.40MM; Library Path: Y:\MIS_DATABASE\Library\ALTIUM_TOOL\SCHEMATICS_PARTS\MS_DISCRETE_Library.schlib; Mfr_name: VISHAY; Mfr_part_number: CRCW04020000Z0ED; Mistral Part No: 110010080019-R; Package: 0402; Part_type: RESISTORS\FIXED; Project: PB_BUGBASE; RoHS: RoHS; Temperature: -55°C+155°C; Tolerance: NA; Voltage: NA; Wattage: 1/16W; Weight: 0.65mg; Datasheet: Y:\MIS_DATABASE\DATASHEETS\RESISTORS\CRCW0603.PDF
R468 R485 = RESISTOR: RES 10K 1/20W 1% 0201; Chkd/date: MANIRAJA/260618; Crtd /date: ALVY/260618; Custom_Duty: 15%; Customs_HS_Code: 85332119; Distributor_name: DIGIKEY; Distributor_part_number: 541-10.0KABCT-ND; Footprint Path: Y:\MIS_DATABASE\Library\ALTIUM_TOOL\PCB_FOOTPRINTS\Altium_Footprint_Lib.PcbLib; Height: 0.28MM; Library Path: Y:\MIS_DATABASE\Library\ALTIUM_TOOL\SCHEMATICS_PARTS\MS_DISCRETE_Library.schlib; Mfr_name: VISHAY; Mfr_part_number: CRCW020110K0FNED; Mistral Part No: 110018060032-R; Package: 0201; Part_type: RESISTORS\FIXED; Project: NEXTNAV_LPRX_BOARD; RoHS: RoHS; Temperature: -55°C+155°C; Tolerance: 1%; Voltage: NA; Wattage: 1/20W; Weight: 0.17mg; Datasheet: Y:\MIS_DATABASE\DATASHEETS\RESISTORS\CRCW0201.PDF
TP58 = TESTPOINT: TESTPOINT CIR 20 SMD; Chkd/date: SHREESHAIL/171006; Crtd /date: MAZHAR/171006; Custom_Duty: NA; Customs_HS_Code: NA; Distributor_name: NA; Distributor_part_number: NA; Footprint Path: Y:\MIS_DATABASE\Library\ALTIUM_TOOL\PCB_FOOTPRINTS\Altium_Footprint_Lib.PcbLib; Height: NA; Library Path: Y:\MIS_DATABASE\Library\ALTIUM_TOOL\SCHEMATICS_PARTS\MS_DISCRETE_Library.schlib; MECHANICAL 3D STEP FILE: NA; Mfr_name: LOCAL; Mistral Part No: NA; Package: SMD; Project: BT MODULE_CSRBC04; RoHS: NA; Temperature: NA; Tolerance: NA; Voltage: NA; Wattage: NA; Weight: NA; Datasheet: NA
U34 = W25Q80BWSNIG_SOIC8: IC SERIAL FLASH MEMORY SOIC8; Chkd/date: VASANTHA/150217; Crtd /date: MANIRAJA/150217; Custom_Duty: 15%; Customs_HS_Code: 85423100; Distributor_name: DIGIKEY; Distributor_part_number: W25Q80DVSNIG CT-ND; Height: 1.75MM; Mfr_name: WINBOND; Mfr_part_number: W25Q80DVSNIG-TR; Mistral Part No: 141117020010-R; Package: SOIC8; Part_type: ICS\DIGITAL\MEMORY; Project: SD820_NANO_SOM; RoHS: RoHS; Temperature: -40°C+85°C; Tolerance: NA; Voltage: NA; Wattage: NA; Weight: NA; Datasheet: Y:\MIS_DATABASE\DATASHEETS\ICS\MEMORY\W25Q80DVSS.PDF
U90 = TPS65988DJ_VQFN56: IC 2-PORT USB TYPE-C AND USB PD CONTROLLER WITH INTEGRATED POWER SWITCH VQFN56; Chkd/date: MANIRAJA/290721; Crtd /date: ALVY/280721; Custom_Duty: 15%; Customs_HS_Code: 85423100; Distributor_name: DIGIKEY; Distributor_part_number: 296-52068-1-ND; Footprint Path: Y:\MIS_DATABASE\Library\ALTIUM_TOOL\PCB_FOOTPRINTS\Altium_Footprint_Lib.PcbLib; Height: 1.00MM; Library Path: Y:\MIS_DATABASE\Library\ALTIUM_TOOL\SCHEMATICS_PARTS\MS_MISCPOWER_Library.schlib; Mfr_name: TEXAS INSTRUMENTS; Mistral Part No: 142021070017-R; Package: VQFN56; Part_type: ICS\POWER\MANAGEMENT; Project: TI_AM62x_SKEVM; RoHS: RoHS; Temperature: -10°C+75°C; Tolerance: NA; Voltage: NA; Wattage: NA; Weight: 127.6mg; Datasheet: Y:\MIS_DATABASE\DATASHEETS\ICS\POWER\TPS65988DHRSHR.PDF
U91 = TVS2200_WSON6: IC 22V FLAT-CLAMP SURGE PROTECTION DEVICE WSON6; Chkd/date: MANIRAJA/011021; Crtd /date: ALVY/011021; Custom_Duty: 15%; Customs_HS_Code: 85423100; Distributor_name: DIGIKEY; Distributor_part_number: 296-52187-1-ND; Footprint Path: Y:\MIS_DATABASE\Library\ALTIUM_TOOL\PCB_FOOTPRINTS\Altium_Footprint_Lib.PcbLib; Height: 0.80MM; Library Path: Y:\MIS_DATABASE\Library\ALTIUM_TOOL\SCHEMATICS_PARTS\MS_MISCPOWER_Library.schlib; Mfr_name: TEXAS INSTRUMENTS; Mistral Part No: 142021100001-R; Package: WSON6; Part_type: ICS\POWER; Project: TI_AM62x SKEVM_BRD; RoHS: RoHS; Temperature: -40°C+125°C; Tolerance: NA; Voltage: NA; Wattage: NA; Weight: 12mg; Datasheet: Y:\MIS_DATABASE\DATASHEETS\ICS\POWER\TVS2200.PDF

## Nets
DGND: C105.2 C113.2 C116.2 C117.2 C118.2 C120.2 C121.1 C122.2 C123.1 C126.2 C128.2 C130.2 C131.2 C132.2 C410.2 C415.2 C417.2 C423.2 C428.2 C436.2 C449.2 C450.2 D4.2(ANODE) D10.2(ANODE) J11.2 J11.10 J13.A1(GND) J13.A12(GND) J13.B1(GND) J13.B12(GND) LD4.1(CATHODE) Q9.4(S1) Q9.7(S2) R157.2 R413.1 R424.2 R429.2 R445.2 R453.2 U34.4(GND) U90.20(GND) U90.51(GND) U90.59(GND) U91.1(GND) U91.2(GND) U91.3(GND) U91.7(GND) ; also on sheet 10 11 12 13 14 15 16 17 18 19 20 21 22 23 24 25 26 27 28 29 30 31 32 33 34 35 36 37 38 39 40 41 42 43
VBUS_TYPEC1: C118.1 C415.1 C417.1 J13.A4(VBUS1) J13.A9(VBUS2) J13.B4(VBUS3) J13.B9(VBUS4) R160.1 U90.13(VBUS1) U91.4(IN1) U91.5(IN2) U91.6(IN3)
VBUS_TYPEC2: C126.1 C423.1 C428.1 C449.1 C450.1 C455.1 Q11.4(D1) Q11.7(D2) R485.1 U90.3(VBUS2) ; also on sheet 34 35
VCC_3V3_SYS: R167.1 ; also on sheet 10 12 13 17 18 19 21 22 23 25 26 28 29 30 32 33 34 35 36 37 38 39 40 41 42
VCC_5V0: C436.1 C444.1 Q10.4(D1) Q10.7(D2) R447.1 R468.1 ; also on sheet 10 32 34 37 40
ADCIN1: R428.2 R429.1 U90.6(ADCIN1)
ADCIN2: R424.1 R425.2 U90.10(ADCIN2)
DRAIN1: U90.8(DRAIN1_1) U90.15(DRAIN1_2) U90.19(DRAIN1_3) U90.58(DRAIN1_4)
DRAIN2: U90.7(DRAIN2_1) U90.52(DRAIN2_2) U90.56(DRAIN2_3) U90.57(DRAIN2_4)
LDO_1V8: C122.1 U90.35(LDO_1V8)
LDO_3V3: C105.1 C121.2 R142.1 R145.1 R146.1 R147.1 R158.1 R161.1 R412.1 R414.1 R415.1 R419.1 R425.1 R428.1 U34.8(VCC) U90.9(LDO_3V3) ; also on sheet 12
P2_PP_EXT_ENABLE: R449.1 U90.49(GPIO17/PP_EXT2)
PD_GPIO0: R416.2 U90.16(GPIO0)
PD_GPIO2: TP58.1(TP) U90.18(GPIO2)
PD_HRESET: R445.1 U90.44(HRESET)
PD_I2C_IRQ: R167.2 R169.1 ; also on sheet 39
PD_M_I2C3_IRQ: R412.2 U90.23(~{I2C3_IRQ}/GPIO7)
PD_M_I2C3_SCL: R161.2 R395.1 U90.21(I2C3_SCL/GPIO5)
PD_M_I2C3_SDA: R158.2 R396.1 U90.22(I2C3_SDA/GPIO6)
PD_MS_I2C1_IRQ: R419.2 U90.29(~{I2C1_IRQ})
PD_MS_I2C1_SCL: R393.1 R415.2 U90.27(I2C1_SCL)
PD_MS_I2C1_SDA: R394.1 R414.2 U90.28(I2C1_SDA)
PD_S_I2C2_IRQ: R169.2 U90.34(~{I2C2_IRQ})
PD_S_I2C2_SCL: R421.2 U90.32(I2C2_SCL)
PD_S_I2C2_SDA: R422.2 U90.33(I2C2_SDA)
PD_SPI_CLK: J11.7 R436.2 U34.6(CLK)
PD_SPI_MISO: J11.5 R146.2 R426.2 U34.2(DO(IO1))
PD_SPI_MOSI: J11.8 R431.2 U34.5(DI(IO0))
PD_SPI_SS: J11.9 R147.2 R439.2 U34.1(~{CS})
PD_VIN_3V3: C123.2 U90.5(VIN_3V3)
PP1_CABLE: C117.1 U90.25(PP1_CABLE)
PP2_CABLE: R447.2 U90.46(PP2_CABLE)
SoC_I2C0_SCL: R421.1 ; also on sheet 12 21 32 41
SoC_I2C0_SDA: R422.1 ; also on sheet 12 21 32 41
SoC_USB0_DRVVBUS: R416.1 R446.1 ; also on sheet 34
SPI_HOLDn: R145.2 U34.7(~{HOLD}(IO3))
SPI_WPn: R142.2 U34.3(~{WP}(IO2))
USB_TYPEC1_EARTH: C410.1 J13.SH1 J13.SH2 J13.SH3 J13.SH4 R157.1
USBC_CONN1_CC1: C113.1 D4.1(CATHODE) J13.A5(CC1) U90.24(C1_CC1)
USBC_CONN1_CC2: C116.1 D10.1(CATHODE) J13.B5(CC2) U90.26(C1_CC2)
USBC_CONN2_CC1: C131.1 U90.45(C2_CC1) ; also on sheet 35
USBC_CONN2_CC2: C130.1 U90.47(C2_CC2) ; also on sheet 35
VMAIN: C120.1 C128.1 C132.1 U90.1(PP_HV2) U90.11(PP_HV1) ; also on sheet 10 11 25
N17370891: R413.2 U90.17(GPIO1)
N17824845: R426.1 U90.36(SPI_MISO/GPIO8)
N17824852: R431.1 U90.37(SPI_MOSI/GPIO9)
N17824859: R436.1 U90.38(SPI_CLK/GPIO10)
N17824866: R439.1 U90.39(~{SPI_SS}/GPIO11)
N17827086: J11.1 R393.2 R395.2
N17827089: J11.3 R394.2 R396.2
N17849698: C445.1 Q10.1(S1) Q10.2(S2) Q10.5(S3) Q10.6(S4) Q10.8(S5) Q11.1(S1) Q11.2(S2) Q11.5(S3) Q11.6(S4) Q11.8(S5) R475.1
N17850096: C444.2 C445.2 C455.2 Q10.3(G) Q11.3(G) R467.1 R468.2 R475.2 R485.2
N17935978: Q9.3(G) R446.2 R449.2 R453.1
N17936309: Q9.1(D1) Q9.2(D2) Q9.5(D3) Q9.6(D4) Q9.8(D5) R467.2
N22682365: LD4.2(ANODE) R160.2

Not connected (* = marked no-connect by the designer): J11 4* 6*; J13 A2(TX1+)* A3(TX1-)* A6(D+_1)* A7(D-_1)* A8(SBU1)* A10(RX2-)* A11(RX2+)* B2(TX2+)* B3(TX2-)* B6(D+_2)* B7(D-_2)* B8(SBU2)* B10(RX1-)* B11(RX1+)*; U90 30(HPD1/GPIO3)* 31(HPD2/GPIO4)* 40(GPIO12)* 41(GPIO13)* 42(GPIO14/PWM)* 43(GPIO15/PWM)* 48(GPIO16/PP_EXT1)* 50(C1_USB_P/GPIO18)* 53(C1_USB_N/GPIO19)* 54(C2_USB_P/GPIO20)* 55(C2_USB_N/GPIO21)*

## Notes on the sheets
sheet 1
- AM62A7 / AM62A3 LOW POWER STARTER KIT SK (EVM)
                         WITH TPS65931211-Q1 PMIC
- TABLE OF CONTENTS
- Revision Number
- PAGE
- CONTENTS
- PAGE
- CONTENTS
- REV
- A
- 01
- TABLE OF CONTENTS
- 23
- CPSW3G  RGMII_2 ETHERNET PHY
- VER
- 1.1
- 02
- REVISION HISTORY
- 24
- SOC MAC INTERFACE, CLOCK BUFFER FOR SOC AND ETHERNET PHYS
- 03
- BLOCK DIAGRAM SK-AM62A-LP
- 25
- TEST AUTOMATION
- 04
- BLOCK DIAGRAM XDS110 DEBUGGER
- 26
- BOOT MODE CONFIGURATION BUFFERS, RESISTOR DIVIDERS AND DIP SWITCHES
- 05
- POWER ARCHITECTURE BLOCK DIAGRAM
- 27
- XDS110 DEBUGGER
- 06
- POWER-UP AND POWER-DOWN SEQUENCE
- 28
- SOC JTAG INTERFACE & JTAG BUFFERS
- 07
- I2C TREE
- 29
- JTAG 20 PIN cTI CONNECTOR AND BUFFERS
- 08
- GPIO MAPPING TABLE
- 30
- FT4232 UART TO USB BRIDGE
- 09
- USB TYPE-C PD CONTROLLER AND  POWER SUPPLY
- 31
- SOC WKUP AND SOC GPMC INTERFACE
- 10
- PERIPHERAL POWER SUPPLIES - 1
- 32
- USER EXPANSION CONNECTOR
- 11
- PERIPHERAL POWER SUPPLIES - 2
- 33
- SOC-MCU DOMAIN IO and OSC0 AND SOC-MCU IO HEADER
- 12
- SOC POWER SUPPLIES - USING PMIC
- 34
- SOC USB INTERFACE, USB1 TYPE A CONNECTOR, VBUS DIVIDER AND POWER SWITCH
- 13
- SOC SUPPLY RAILS CURRENT MONITORING
- 35
- USB0 TYPE-C DRP & TEST LEDs
- 14
- SOC SUPPLY RAILS AND POWER SUPPLIES
- 36
- SoC UART1 FET SWITCH & BUFFER
- 15
- CAPS FOR SOC POWER SUPPLIES AND SOC GROUND VSS
- 37
- SOC CSI INTERFACE,  BIDIRECTIONAL PASSIVE SWITCH AND CAMERA CONNECTOR
- 16
- SOC DDRSS AND LPDDR4 MEMORY DEVICE INTERFACE
- 38
- AUDIO CODEC
- 17
- M.2 INTERFACE AND CONNECTOR
- 39
- IO EXPANDER AND MCASP1 FET SWITCH AND BUFFER
- 18
- SOC MMC0..2 INTERFACE, eMMC FLASH AND eMMC FLASH RESET
- 40
- SOC DPI INTERFACE, DPI TO HDMI TRANSMITTER INTERFACE
- 19
- SD CARD - LOAD SWITCH, LOAD SWITCH RESET LOGIC AND DATA INTERFACE
- 41
- SOC RESET AND IOS, FET SWITCH , AND EXTERNAL LVCMOS CLOCK (OSCILLATOR)
- 20
- SOC OSPI/QSPI INTERFACE, OSPI FLASH AND OSPI FLASH RESET
- 42
- SOC PUSH BUTTON RESET INPUTS, DEBOUNCE LOGIC FOR RC RESET
- 21
- BOARD ID EEPROM & DIGITAL TEMPERATURE SENSORS
- 43
- EXTERNAL SWITCH FOR CAN FD WKUP
- 22
- CPSW3G  RGMII_1 ETHERNET PHY
- 44
- ASSEMBLY NOTES AND MOUNTING HARDWARE
- D-Note :-
- SK/EVM is a device evaluation board or platform. The SK/EVM is not a reference design. In some cases the EVM implementation may deviate from the optimum
  solution to provide a better customer experience or provide flexibility for customers to be able to validate the SOC functionality. TI expects and
  recommends customers to carefully review and follow all requirements defined in the datasheet, silicon errata, and TRM when designing their custom board.
  The information found in the datasheet should always take precedence over the SK/EVM implementation.
- R-Note :-
- * Verify the DNI components configuration with respect to the SK schematics (Use PDF) after completion of board design before board assembly
  * A standard 5% tolerance resistor can be used for most of the series and parallel pull resistor
  * Be sure to read through all the D-Notes (Design notes), R-Notes (Review notes) and CAD notes during board design and before start of board build.
  (Refer FAQs listed for additional details)
- KEY LINKS TO COLLATERALS
- Hardware Design Guide :
- https://www.ti.com/lit/an/sprad85/sprad85.pdf
- Schematic Design and Review Checklist :
- https://www.ti.com/lit/an/sprad21d/sprad21d.pdf
- PMIC Power Solutions Application Note :
- https://www.ti.com/lit/po/slvt204/slvt204.pdf
- DDR Board Design and Layout Guidelines :
- https://www.ti.com/lit/an/sprad66a/sprad66a.pdf
- SKs (Starter Kits) for reference :
  SK-AM62B, SK-AM62B-P1, SK-AM62-LP, SK-AM62-SIP, SK-AM62A-LP, SK-AM62P-LP
sheet 2
- REVISION HISTORY
- VER #
- DATE
- DESCRIPTION OF CHANGES
- AUTHOR
- REVIEWED  BY
- APPROVED  BY
- 0.1
- 09 AUG 2023
- Drafted from "PROC135E3_SCH" document.
- Mistral Design Team
- Nishant
- Ajit MB
- 0.2
- 18 AUG 2023
- Updated SoC, eMMC & PMIC Part Number
- Mistral Design Team
- Nishant
- Ajit MB
- 1.0
- 21 AUG 2023
- Baselined and Released
- Mistral Design Team
- Nishant
- Ajit MB
- Updated SoC Pin name (VMON_VSYS), Enabled Voltage ratings for all the capacitors and added
  Design Review notes
- Moved to DNI : C33, C36, C291, C177, R272, U56, Y1
- Moved to Mount : C556, R295, R296, R297, R299, R300, R301, R302, R303, R505, R534
- 1.1
- 11 JUNE 2024
- C290 - 1uF changed to 2.2uF; C288,C184,C181,C39 - 1uF changed to 0.1uF; C45,C42 - 9pF
  changed to 18pF; C182,C179 - 2.2uF changed to 1uF; C40 - 4.7uF changed to 1uF;
  C38 - 0.1uF changed to 4.7uF
- Mistral Design Team
- R350 - 2.2K changed to 10K; R125,R135 - 3.4K_1%  changed to 3.48K_1%; R343 - 22E changed to
  0E; R315,R242,R371 - 49.9K_1% changed to 10K; R368 - 10K_1% changed to Std 10K; R311 - 100K
  changed to Std 10K; R342,R341,R586,R584 - 22E_1% changed to 0E; R331,R344,R328 - 499E_0.1%
  changed to 499_1%; R451 - 10K changed to 47K; R351,R611 - 11K_1% changed to 10K_1%.
- LINKS TO KEY FAQs
- https://e2e.ti.com/support/processors-group/processors/f/processors-forum/1203305/faq-am62a7-and-am62a7-q1-custom-board-hardware-design-
  collaterals-to-get-started
- https://e2e.ti.com/support/processors-group/processors/f/processors-forum/1203441/faq-am62a3-and-am62a3-q1-custom-board-hardware-design-
  collaterals-to-get-started
- https://e2e.ti.com/support/processors-group/processors/f/processors-forum/1306030/faq-am62p-am62p-q1-custom-board-hardware-design--
  -faqs-related-to-processor-collaterals-functioning-peripherals-interface-and-starter-kit
- https://e2e.ti.com/support/processors-group/processors/f/processors-forum/1340905/faq-am62a7-am62a7-q1-am62a3-am62a3-q1---custom-board
  -hardware-design---guidelines-for-reuse-of-sk-am62a-lp-schematics
- https://e2e.ti.com/support/processors-group/processors/f/processors-forum/1347063/faq-am62a7-and-am62a7-q1-am62a3-and-am62a3-q1---
  custom-board-hardware-design---design-and-review-notes-for-reuse-of-sk-am62a-lp-schematics
- https://e2e.ti.com/support/processors-group/processors/f/processors-forum/1280753/faq-am62a7-am62a7-q1-am62a3-am62a3-q1-custom-board-
  hardware-design---faqs-related-to-processor-collaterals-functioning-peripherals-interface-and-starter-kit
sheet 3
- BLOCK DIAGRAM SK-AM62A-LP
sheet 4
- BLOCK DIAGRAM_XDS110
sheet 5
- POWER BLOCK DGM
sheet 6
- POWER SEQUENCE
sheet 7
- I2C TREE
sheet 8
- GPIO MAPPING TABLE
sheet 9
- USB TYPE-C PD CONTROLLER AND POWER SUPPLY
- Silk: TYPE-C PWR
- TYPE-C DUAL PD CONTROLLER
- POWER INDICATION LED: VBUS_TYPEC1
- D-Note :-
  Ok to use a
  1K standard
  5% tolerance
  resistor
- BP_NoWait
  Safe Configuration
- R-Note :-
  This is a
  supply
  negotiation
  indicator.
  On indicates
  success.
- EXTERNAL POWER PATH FOR SOURCING, 5V/0.5A
- D-Note :-
  Refer AM62P implementation
  for adding the capacitors
- I2C Slave
   Address
- Port1
- Port2
- I2C2(Default)
- 0x38
- 0x3F
- I2C1
- 0x20
- 0x24
- SPI EEPROM & PROGRAMMING HEADER
